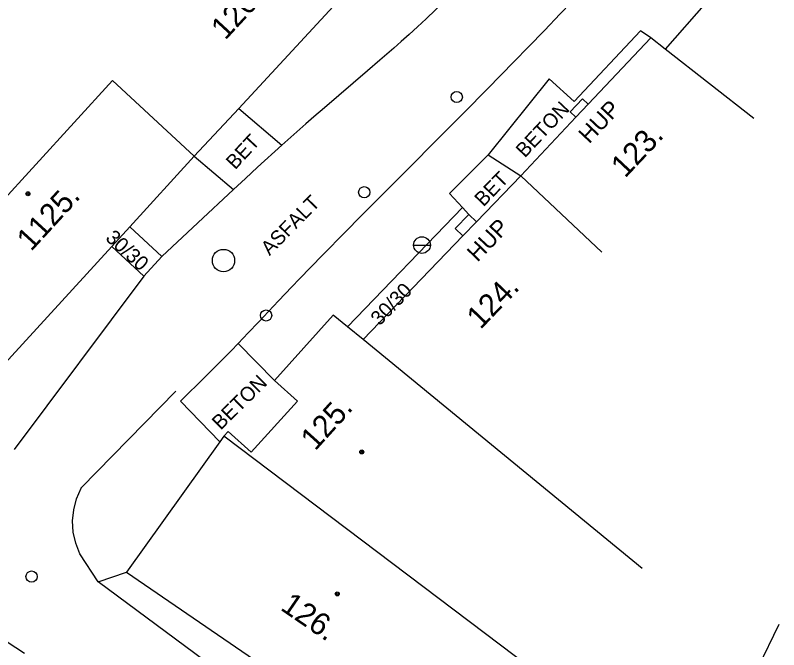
# Model space of a CAD drawing. Extents: x -539244 to -537359, y -1183785 to -1181851.
# Drawn here: x -538505.93 to -538471.69, y -1183434.91 to -1183406.45 of the extents above; entities that cross this region are included whole.
import ezdxf

# ---------------------------------------------------------------- set-up
doc = ezdxf.new("R2010")
doc.units = 0
for name, color, linetype in [('Vrstva 10', 7, 'Continuous'), ('Vrstva 11', 7, 'Continuous'), ('Vrstva 24', 7, 'Continuous'), ('Vrstva 27', 7, 'Continuous'), ('Vrstva 28', 7, 'Continuous'), ('Vrstva 35', 7, 'Continuous'), ('Vrstva 39', 7, 'Continuous'), ('Vrstva 40', 7, 'Continuous'), ('Vrstva 41', 7, 'Continuous'), ('Vrstva 47', 7, 'Continuous'), ('Vrstva 5', 7, 'Continuous')]:
    doc.layers.add(name, color=color, linetype=linetype)

msp = doc.modelspace()

# ---------------------------------------------------------------- linework, layer by layer
at = {"layer": 'Vrstva 10'}
for p, q in [((-538488.952, -1183407.925), (-538489.577, -1183408.472)), ((-538485.802, -1183410.812), (-538489.502, -1183414.531)), ((-538502.97, -1183427.65), (-538498.73, -1183423.32)), ((-538516.91, -1183427.65), (-538505.52, -1183435.06)), ((-538502.21, -1183431.87), (-538503.03, -1183430.61)), ((-538496.58, -1183436.03), (-538502.21, -1183431.87))]:
    msp.add_line(p, q, dxfattribs=at)
for points in [[(-538482.27, -1183401.19), (-538482.807, -1183401.775), (-538483.279, -1183402.285), (-538483.695, -1183402.73), (-538484.06, -1183403.117), (-538484.702, -1183403.792), (-538485.187, -1183404.296), (-538485.553, -1183404.671), (-538486.104, -1183405.232), (-538486.66, -1183405.79), (-538486.878, -1183406.005), (-538487.09, -1183406.212), (-538487.505, -1183406.608), (-538487.898, -1183406.975), (-538488.27, -1183407.315), (-538488.621, -1183407.631), (-538488.952, -1183407.925)], [(-538480.388, -1183405.231), (-538481.013, -1183405.896), (-538481.485, -1183406.392), (-538482.196, -1183407.133), (-538482.91, -1183407.87), (-538483.548, -1183408.524), (-538484.748, -1183409.746), (-538485.802, -1183410.812)], [(-538489.577, -1183408.472), (-538490.127, -1183408.947), (-538492.061, -1183410.6), (-538492.542, -1183411.015), (-538492.902, -1183411.328), (-538493.438, -1183411.802), (-538493.97, -1183412.28), (-538495.064, -1183413.271), (-538495.609, -1183413.768), (-538496.15, -1183414.27)], [(-538496.15, -1183414.27), (-538497.75, -1183415.77), (-538499.35, -1183417.27)], [(-538489.502, -1183414.531), (-538490.425, -1183415.462), (-538491.117, -1183416.161), (-538492.151, -1183417.213), (-538493.18, -1183418.27), (-538493.527, -1183418.631), (-538494.13, -1183419.266), (-538495.029, -1183420.224), (-538495.478, -1183420.703), (-538495.93, -1183421.18), (-538496.248, -1183421.509)], [(-538499.35, -1183417.27), (-538500.162, -1183418.153), (-538505.98, -1183425.93)], [(-538496.248, -1183421.509), (-538496.529, -1183421.794), (-538497.026, -1183422.288), (-538497.775, -1183423.025), (-538498.149, -1183423.396), (-538498.52, -1183423.77)], [(-538503.03, -1183430.61), (-538503.217, -1183430.138), (-538503.328, -1183429.642), (-538503.36, -1183429.136), (-538503.311, -1183428.63), (-538503.185, -1183428.139), (-538502.982, -1183427.673), (-538502.97, -1183427.65)]]:
    msp.add_lwpolyline(points, dxfattribs=at)
at = {"layer": 'Vrstva 11'}
for p, q in [((-538477.89, -1183407.15), (-538480.87, -1183410.32)), ((-538477.43, -1183407.46), (-538477.89, -1183407.15)), ((-538481.98, -1183409.3), (-538484.72, -1183412.71)), ((-538480.87, -1183410.32), (-538481.98, -1183409.3)), ((-538495.91, -1183410.629), (-538493.97, -1183412.28)), ((-538497.9, -1183412.78), (-538496.15, -1183414.27)), ((-538486.45, -1183414.45), (-538484.72, -1183412.71)), ((-538484.72, -1183412.71), (-538483.26, -1183413.65)), ((-538485.876, -1183415.072), (-538491.03, -1183420.43)), ((-538500.797, -1183415.945), (-538499.35, -1183417.27)), ((-538501.607, -1183416.83), (-538500.162, -1183418.153)), ((-538494.31, -1183422.83), (-538495.93, -1183421.18)), ((-538498.52, -1183423.77), (-538496.754, -1183425.583)), ((-538502.21, -1183431.87), (-538500.94, -1183431.43))]:
    msp.add_line(p, q, dxfattribs=at)
msp.add_lwpolyline([(-538485.587, -1183415.384), (-538485.876, -1183415.072), (-538486.45, -1183414.45)], dxfattribs=at)
at = {"layer": 'Vrstva 24'}
for p, q in [((-538481.047, -1183410.791), (-538480.49, -1183410.2)), ((-538480.236, -1183410.439), (-538480.49, -1183410.2)), ((-538480.793, -1183411.031), (-538481.047, -1183410.791)), ((-538485.587, -1183415.384), (-538486.2, -1183416.02)), ((-538485.245, -1183415.713), (-538485.587, -1183415.384)), ((-538485.857, -1183416.35), (-538486.2, -1183416.02))]:
    msp.add_line(p, q, dxfattribs=at)
at = {"layer": 'Vrstva 27'}
msp.add_circle((-538496.592, -1183417.455), 0.5, dxfattribs=at)
at = {"layer": 'Vrstva 28'}
for centre in [(-538486.13, -1183410.12), (-538490.28, -1183414.39), (-538494.68, -1183419.92), (-538505.2, -1183431.63)]:
    msp.add_circle(centre, 0.25, dxfattribs=at)
at = {"layer": 'Vrstva 35'}
msp.add_line((-538488.065, -1183416.76), (-538487.315, -1183416.76), dxfattribs=at)
msp.add_circle((-538487.69, -1183416.76), 0.375, dxfattribs=at)
at = {"layer": 'Vrstva 39'}
for centre, radius in [((-538505.362, -1183414.462), 0.09), ((-538505.362, -1183414.462), 0.0398), ((-538490.39, -1183426.04), 0.09), ((-538490.39, -1183426.04), 0.0398), ((-538491.488, -1183432.407), 0.09), ((-538491.488, -1183432.407), 0.0398)]:
    msp.add_circle(centre, radius, dxfattribs=at)
at = {"layer": 'Vrstva 5'}
for p, q in [((-538489.25, -1183403.43), (-538495.91, -1183410.629)), ((-538474.942, -1183405.874), (-538476.79, -1183407.97)), ((-538477.43, -1183407.46), (-538480.236, -1183410.439)), ((-538476.79, -1183407.97), (-538477.43, -1183407.46)), ((-538472.802, -1183411.081), (-538476.79, -1183407.97)), ((-538501.57, -1183409.385), (-538510.74, -1183419.41)), ((-538501.57, -1183409.385), (-538497.9, -1183412.78)), ((-538480.236, -1183410.439), (-538480.793, -1183411.031)), ((-538495.91, -1183410.629), (-538497.9, -1183412.78)), ((-538480.793, -1183411.031), (-538483.26, -1183413.65)), ((-538497.9, -1183412.78), (-538500.797, -1183415.945)), ((-538483.26, -1183413.65), (-538485.245, -1183415.713)), ((-538479.62, -1183417.078), (-538483.26, -1183413.65)), ((-538500.797, -1183415.945), (-538501.607, -1183416.83)), ((-538485.245, -1183415.713), (-538485.857, -1183416.35)), ((-538485.857, -1183416.35), (-538490.33, -1183421)), ((-538501.607, -1183416.83), (-538507.09, -1183422.82)), ((-538491.67, -1183419.91), (-538494.31, -1183422.83)), ((-538491.03, -1183420.43), (-538491.67, -1183419.91)), ((-538490.33, -1183421), (-538491.03, -1183420.43)), ((-538477.82, -1183431.27), (-538490.33, -1183421)), ((-538493.278, -1183423.763), (-538494.31, -1183422.83)), ((-538493.278, -1183423.763), (-538495.346, -1183426.05)), ((-538496.378, -1183425.117), (-538496.58, -1183425.34)), ((-538495.346, -1183426.05), (-538496.378, -1183425.117)), ((-538496.754, -1183425.583), (-538500.94, -1183431.43)), ((-538496.58, -1183425.34), (-538496.754, -1183425.583)), ((-538482.18, -1183436.2), (-538496.58, -1183425.34)), ((-538500.94, -1183431.43), (-538494.53, -1183435.82)), ((-538471.69, -1183433.78), (-538477.18, -1183445.11))]:
    msp.add_line(p, q, dxfattribs=at)

# ---------------------------------------------------------------- texts
at = {"layer": 'Vrstva 40'}
for s, rotation, p in [('BETON', 46.7155, (-538483.076, -1183412.877)), ('BET', 47.227, (-538496.068, -1183413.41)), ('BET', 46.1124, (-538484.932, -1183415.072)), ('ASFALT', 45.5401, (-538494.522, -1183417.266)), ('30/30', 317.5241, (-538501.923, -1183416.497)), ('30/30', 46.1124, (-538489.591, -1183420.413)), ('BETON', 44.5237, (-538496.721, -1183425.089))]:
    msp.add_text(s, height=0.65, rotation=rotation, dxfattribs=at).set_placement(p)
at = {"layer": 'Vrstva 41'}
for rotation, p in [(46.7155, (-538480.191, -1183412.25)), (46.1124, (-538485.201, -1183417.554))]:
    msp.add_text('HUP', height=0.75, rotation=rotation, dxfattribs=at).set_placement(p)
at = {"layer": 'Vrstva 47'}
for s, rotation, p in [('1269.', 47.227, (-538496.511, -1183407.599)), ('123.', 46.7155, (-538478.58, -1183413.786)), ('1125.', 47.5309, (-538505.221, -1183417.076)), ('124.', 46.1124, (-538485.064, -1183420.574)), ('125.', 47.883, (-538492.48, -1183426.025)), ('126.', 325.594, (-538494.082, -1183433.097))]:
    msp.add_text(s, height=1, rotation=rotation, dxfattribs=at).set_placement(p)

doc.saveas('drawing.dxf')
